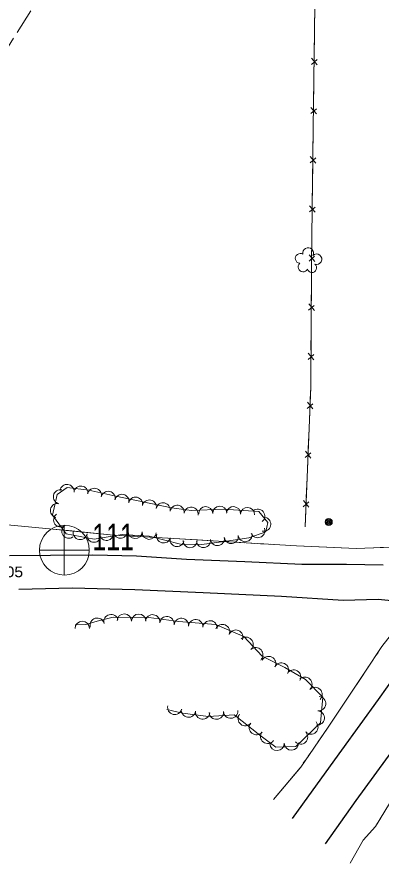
# Model space of a CAD drawing. Extents: x 298072 to 300359, y 47756 to 50122.
# Drawn here: x 298855.4 to 299060, y 48348 to 48823.7 of the extents above; entities that cross this region are included whole.
import ezdxf

# ---------------------------------------------------------------- set-up
doc = ezdxf.new("R2010")
doc.units = 0
doc.header["$LTSCALE"] = 2.4
doc.linetypes.add('LONG_DASHED', pattern=[7.5, 6, -1.5])
for name, color, linetype, lineweight in [('11', 7, 'Continuous', 25), ('14', 7, 'Continuous', 13), ('15', 7, 'Continuous', 13), ('18', 7, 'Continuous', 13), ('19', 7, 'Continuous', 13), ('4', 7, 'Continuous', 13), ('6', 7, 'Continuous', 13)]:
    doc.layers.add(name, color=color, linetype=linetype, lineweight=lineweight)

msp = doc.modelspace()

# ---------------------------------------------------------------- linework, layer by layer
at = {"layer": '11'}
for points in [[(298851.237, 48520.95), (298874.257, 48521.052), (298898.032, 48521.24), (298922.524, 48520.793), (298950.747, 48518.838), (298983.414, 48517.658), (299015.412, 48516.155), (299040.651, 48515.988), (299061.171, 48515.642)], [(298856.43, 48502.098), (298886.422, 48502.837), (298921.67, 48501.855), (298960.034, 48500.114), (299004.015, 48497.993), (299038.664, 48495.79), (299058.368, 48496.338), (299069.567, 48495.309), (299072.437, 48494.733), (299075.152, 48493.629), (299077.868, 48491.528), (299080.463, 48488.49), (299082.145, 48484.904), (299082.73, 48481.177), (299082.533, 48477.203), (299081.364, 48473.612), (299078.474, 48468.424), (299058.337, 48439.986), (299037.794, 48411.569), (299021.737, 48389.305), (299009.962, 48373.031)], [(299028.794, 48358.922), (299046.078, 48383.296), (299067.642, 48413.073), (299091.651, 48445.959), (299111.467, 48473.957), (299120.982, 48485.542), (299127.672, 48489.835), (299133.956, 48492.451), (299144.552, 48493.154), (299154.25, 48492.804), (299171.68, 48493.142), (299195.394, 48493.553), (299227.514, 48493.295), (299259.174, 48491.522), (299287.804, 48491.45), (299322.814, 48490.828), (299355.076, 48490.314), (299380.259, 48489.565), (299413.071, 48489.188)]]:
    msp.add_lwpolyline(points, dxfattribs=at)
at = {"layer": '14'}
for centre, radius in [((299030.557, 48539.778), 2.018), ((299030.545, 48539.783), 1.518), ((299030.581, 48539.765), 1.008), ((299030.575, 48539.774), 0.502)]:
    msp.add_circle(centre, radius, dxfattribs=at)
at = {"layer": '15'}
for p, q in [((299022.526, 48813.371), (299022.661, 48823.245)), ((299022.373, 48802.145), (299022.526, 48813.371)), ((299024.024, 48796.744), (299020.862, 48800.474)), ((299020.814, 48796.957), (299023.997, 48799.686)), ((299022.149, 48785.743), (299022.284, 48795.617)), ((299021.995, 48774.517), (299022.149, 48785.743)), ((299020.436, 48769.329), (299023.619, 48772.059)), ((299023.646, 48769.116), (299020.484, 48772.846)), ((299021.655, 48746.888), (299021.779, 48758.115)), ((299020.11, 48741.696), (299023.285, 48744.434)), ((299023.32, 48741.492), (299020.149, 48745.214)), ((299021.474, 48730.487), (299021.583, 48740.361)), ((299021.349, 48719.26), (299021.474, 48730.487)), ((299019.804, 48714.068), (299022.98, 48716.806)), ((299023.014, 48713.864), (299019.843, 48717.585)), ((299021.168, 48702.858), (299021.277, 48712.732)), ((299021.044, 48691.631), (299021.168, 48702.858)), ((299019.499, 48686.439), (299022.674, 48689.177)), ((299022.709, 48686.235), (299019.538, 48689.957)), ((299020.812, 48664.001), (299020.897, 48675.229)), ((299019.285, 48658.804), (299022.451, 48661.553)), ((299022.496, 48658.611), (299019.312, 48662.322)), ((299020.689, 48647.599), (299020.763, 48657.474)), ((299020.604, 48636.372), (299020.689, 48647.599)), ((299022.288, 48630.982), (299019.104, 48634.692)), ((299019.077, 48631.174), (299022.243, 48633.924)), ((299020.481, 48619.97), (299020.555, 48629.844)), ((299018.474, 48603.604), (299021.729, 48606.246)), ((299021.677, 48603.305), (299018.617, 48607.118)), ((299019.506, 48592.358), (299019.907, 48602.225)), ((299019.05, 48581.14), (299019.506, 48592.358)), ((299017.352, 48575.996), (299020.607, 48578.639)), ((299020.555, 48575.697), (299017.495, 48579.511)), ((299018.384, 48564.751), (299018.785, 48574.617)), ((299017.928, 48553.532), (299018.384, 48564.751)), ((299016.23, 48548.388), (299019.485, 48551.031)), ((299019.433, 48548.089), (299016.373, 48551.903)), ((299017.262, 48537.143), (299017.663, 48547.01))]:
    msp.add_line(p, q, dxfattribs=at)
for points in [[(299017.262, 48537.143), (299020.447, 48615.518), (299020.97, 48684.962), (299021.815, 48761.361), (299022.94, 48843.61), (299024.629, 48929.407), (299024.911, 49009.798), (299026.876, 49077.821), (299026.812, 49087.143)], [(299021.779, 48758.115), (299021.815, 48761.361), (299021.906, 48767.99)], [(299020.897, 48675.229), (299020.97, 48684.962), (299020.972, 48685.104)], [(299020.172, 48608.748), (299020.447, 48615.518), (299020.481, 48619.97)]]:
    msp.add_lwpolyline(points, dxfattribs=at)
at = {"layer": '18'}
msp.add_lwpolyline([(298910.962, 48554.235), (298895.842, 48557.622), (298883.694, 48559.072), (298878.008, 48555.211), (298875.51, 48543.613), (298883.003, 48533.192), (298898.908, 48530.175), (298914.497, 48532.659), (298929.706, 48531.895), (298947.296, 48527.259), (298959.258, 48527.103), (298973.197, 48529.089), (298985.714, 48530.85), (298995.241, 48534.311), (298996.431, 48539.473), (298991.255, 48545.651), (298971.31, 48546.914), (298953.546, 48546.201), (298942.229, 48547.767)], close=True, dxfattribs=at)
msp.add_lwpolyline([(298939.69, 48434.439), (298948.415, 48432.348), (298962.984, 48430.452), (298977.539, 48431.464), (298991.915, 48419.955), (299000.946, 48413.163), (299012.179, 48413.52), (299025.965, 48426.848), (299027.312, 48441.313), (299017.584, 48451.169), (299005.939, 48457.978), (298993.219, 48464.373), (298982.968, 48475.401), (298966.925, 48482.111), (298946.302, 48483.909), (298929.588, 48486.07), (298909.572, 48486.261), (298901.235, 48484.158), (298893.994, 48482.073), (298888.08, 48482.051)], dxfattribs=at)
for centre, radius, start, end in [((299019.009, 48690.977), 2.974, 332.88471, 194.11859), ((299014.566, 48687.953), 2.777, 55.8556, 263.62859), ((299023.707, 48687.484), 2.975, 250.53553, 133.5088), ((299016.139, 48683.142), 2.783, 132.53262, 333.54366), ((299021.15, 48682.589), 2.611, 195.24076, 53.17337), ((298883.59, 48557.007), 3.942, 353.20097, 173.18565), ((298891.416, 48556.073), 3.942, 353.20097, 173.18565), ((298898.974, 48554.806), 3.942, 347.38139, 167.36607), ((298879.842, 48553.929), 3.942, 77.85286, 257.83754), ((298906.665, 48553.084), 3.942, 347.38139, 167.36607), ((298914.403, 48551.417), 3.942, 348.32011, 168.30479), ((298922.121, 48549.82), 3.942, 348.32011, 168.30479), ((298878.182, 48546.223), 3.942, 77.85286, 257.83754), ((298929.84, 48548.223), 3.942, 348.32011, 168.30479), ((298937.559, 48546.627), 3.942, 348.32011, 168.30479), ((298945.452, 48545.238), 3.942, 352.12934, 172.11401), ((298961.501, 48544.456), 3.942, 2.30613, 182.29081), ((298969.377, 48544.772), 3.942, 2.30613, 182.29081), ((298977.032, 48544.485), 3.942, 356.38429, 176.36897), ((298879.968, 48540.947), 3.942, 125.72489, 305.70957), ((298953.26, 48544.158), 3.942, 352.12934, 172.11401), ((298984.898, 48543.986), 3.942, 356.38429, 176.36897), ((298990.729, 48543.067), 3.942, 309.96433, 129.94901), ((298994.092, 48538.508), 3.942, 257.02602, 77.01069), ((298884.569, 48534.547), 3.942, 125.72489, 305.70957), ((298890.949, 48533.784), 3.942, 169.26691, 349.25158), ((298913.548, 48534.597), 3.942, 189.06124, 9.04592), ((298921.841, 48534.356), 3.942, 177.13192, 357.11659), ((298929.713, 48533.96), 3.942, 177.13192, 357.11659), ((298990.73, 48534.867), 3.942, 199.9729, 19.95758), ((298898.693, 48532.316), 3.942, 169.26691, 349.25158), ((298905.764, 48533.356), 3.942, 189.06124, 9.04592), ((298937.76, 48531.906), 3.942, 165.24262, 345.22729), ((298945.382, 48529.897), 3.942, 165.24262, 345.22729), ((298960.232, 48529.326), 3.942, 188.11647, 8.10115), ((298968.035, 48530.437), 3.942, 188.11647, 8.10115), ((298975.843, 48531.544), 3.942, 188.01597, 8.00064), ((298983.648, 48532.643), 3.942, 188.01597, 8.00064), ((298952.682, 48529.252), 3.942, 179.26049, 359.24517), ((298908.291, 48483.758), 4.039, 14.16512, 194.1498), ((298915.774, 48484.088), 4.039, 359.46094, 179.44562), ((298923.851, 48484.011), 4.039, 359.46094, 179.44562), ((298931.658, 48483.671), 4.039, 352.6406, 172.62528), ((298939.668, 48482.635), 4.039, 352.6406, 172.62528), ((298892.126, 48479.952), 4.039, 0.2208, 180.20548), ((298900.538, 48481.757), 4.039, 16.07108, 196.05576), ((298947.774, 48481.659), 4.039, 355.02497, 175.00965), ((298955.821, 48480.957), 4.039, 355.02497, 175.00965), ((298963.867, 48480.256), 4.039, 355.02497, 175.00965), ((298970.9, 48478.157), 4.039, 337.31049, 157.29517), ((298978.351, 48475.04), 4.039, 337.31049, 157.29517), ((298984.114, 48471.063), 4.039, 312.91644, 132.90112), ((298989.613, 48465.147), 4.039, 312.91644, 132.90112), ((298996.786, 48460.213), 4.039, 333.31663, 153.30131), ((299004.003, 48456.585), 4.039, 333.31663, 153.30131), ((299010.891, 48452.633), 4.039, 329.69222, 149.67689), ((299017.176, 48448.573), 4.039, 314.63319, 134.61786), ((299022.85, 48442.825), 4.039, 314.63319, 134.61786), ((299024.849, 48437.659), 4.039, 264.68754, 84.67222), ((298944.111, 48435.553), 4.039, 166.53056, 346.51524), ((298951.806, 48434.039), 4.039, 172.5929, 352.57758), ((298959.816, 48432.996), 4.039, 172.5929, 352.57758), ((298967.433, 48432.88), 4.039, 183.985, 3.96968), ((298975.491, 48433.441), 4.039, 183.985, 3.96968), ((298983.678, 48429.257), 4.039, 141.32793, 321.31261), ((299024.1, 48429.616), 4.039, 264.68754, 84.67222), ((298989.984, 48424.209), 4.039, 141.32793, 321.31261), ((299020.546, 48424.549), 4.039, 224.03993, 44.02461), ((298996.311, 48419.294), 4.039, 143.06171, 323.04639), ((299014.739, 48418.935), 4.039, 224.03993, 44.02461), ((299001.567, 48415.298), 4.039, 181.82799, 1.81266), ((299009.64, 48415.554), 4.039, 181.82799, 1.81266)]:
    msp.add_arc(centre, radius, start, end, dxfattribs=at)
at = {"layer": '19'}
for p, q in [((298914.219, 48532.159), (298916.036, 48532.057)), ((298919.668, 48531.854), (298921.484, 48531.752)), ((298925.117, 48531.548), (298926.933, 48531.446)), ((298956.899, 48529.705), (298983.23, 48528.108)), ((298986.862, 48527.888), (298988.678, 48527.777)), ((298992.309, 48527.557), (298994.125, 48527.447)), ((298997.757, 48527.227), (298999.573, 48527.116)), ((299059.542, 48525.431), (299061.36, 48525.502)), ((299057.368, 48465.098), (299058.257, 48466.426)), ((299052.038, 48457.127), (299052.926, 48458.456)), ((299054.703, 48461.113), (299055.592, 48462.441)), ((299021.766, 48412.009), (299022.676, 48413.324)), ((299019.038, 48408.066), (299019.947, 48409.38)), ((298999.485, 48383.835), (299014.441, 48401.532)), ((299016.31, 48404.123), (299017.219, 48405.437))]:
    msp.add_line(p, q, dxfattribs=at)
for points in [[(298811.934, 48539.27), (298819.663, 48539.989), (298842.165, 48538.9), (298875.536, 48535.803), (298909.762, 48532.409), (298943.635, 48530.51), (299012.386, 48526.339), (299045.94, 48524.905), (299065.344, 48525.656), (299080.022, 48527.572), (299090.397, 48526.576), (299095.491, 48526.071), (299097.133, 48525.348), (299095.618, 48521.498), (299095.393, 48520.904)], [(298858.077, 48537.423), (298875.536, 48535.803), (298884.335, 48534.93)], [(298884.335, 48534.93), (298909.762, 48532.409), (298910.587, 48532.363)], [(298930.566, 48531.243), (298943.635, 48530.51), (298956.899, 48529.705)], [(299003.205, 48526.896), (299012.386, 48526.339), (299029.551, 48525.605)], [(299029.551, 48525.605), (299045.94, 48524.905), (299055.906, 48525.291)], [(298999.485, 48383.835), (299014.86, 48402.028), (299029.947, 48423.832), (299041.41, 48441.4), (299051.257, 48455.959), (299060.455, 48469.714), (299067.08, 48478.42), (299071.029, 48484.414), (299073.099, 48488.131)], [(299042.661, 48348.046), (299049.896, 48360.957), (299056.841, 48368.536), (299064.79, 48381.456), (299072.216, 48391.854), (299082.226, 48406.304), (299094.63, 48422.381), (299106.961, 48440.554), (299119.285, 48457.527), (299127.615, 48468.6), (299134.966, 48478.728), (299138.814, 48483.98), (299140.713, 48487.491)], [(299037.375, 48435.216), (299041.41, 48441.4), (299050.254, 48454.476)], [(299024.495, 48415.952), (299029.947, 48423.832), (299037.375, 48435.216)], [(299042.661, 48348.046), (299049.896, 48360.957), (299056.841, 48368.536), (299059.915, 48373.533)]]:
    msp.add_lwpolyline(points, dxfattribs=at)
at = {"layer": '4', "linetype": 'LONG_DASHED'}
msp.add_line((299332.839, 49573.576), (298725.651, 48608.445), dxfattribs=at)
at = {"layer": '4'}
for p, q in [((298882.053, 48537.953), (298881.988, 48510.099)), ((298868.144, 48523.923), (298896.049, 48523.91))]:
    msp.add_line(p, q, dxfattribs=at)
msp.add_circle((298882.105, 48523.931), 14, dxfattribs=at)

# ---------------------------------------------------------------- texts
at = {"layer": '4', "width": 0.7}
msp.add_text('111', height=15, dxfattribs=at).set_placement((298897.757, 48523.861))
at = {"layer": '6', "width": 1.1}
msp.add_text('1140.05', height=6, dxfattribs=at).set_placement((298827.001, 48508.751))

doc.saveas('drawing.dxf')
